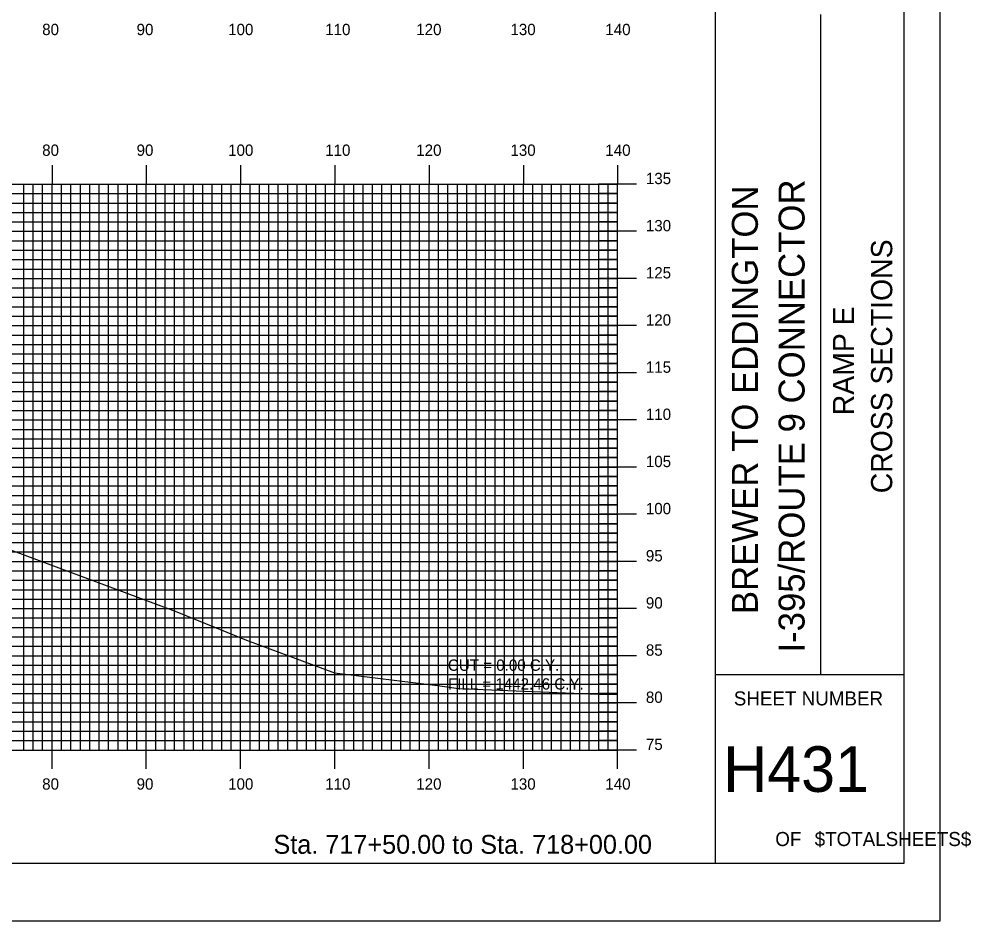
# Model space of a CAD drawing. Extents: x 857265 to 857608, y 364366 to 364586.
# Drawn here: x 857506.8 to 857607.8, y 364365.7 to 364461.3 of the extents above; entities that cross this region are included whole.
import ezdxf

# ---------------------------------------------------------------- set-up
doc = ezdxf.new("R2010")
doc.units = 0
for name, color, linetype in [('BORDER', 7, 'Continuous'), ('D_Text_Standard', 7, 'Continuous'), ('H_V ANNOTATION', 7, 'Continuous'), ('MAJOR', 7, 'Continuous'), ('MINOR', 7, 'Continuous'), ('PLOT BOUNDARY', 7, 'Continuous'), ('S_Roadway_Centerline', 7, 'Continuous')]:
    doc.layers.add(name, color=color, linetype=linetype)

msp = doc.modelspace()

# ---------------------------------------------------------------- linework, layer by layer
at = {"layer": 'BORDER'}
for p, q in [((857580.74, 364371.79), (857580.74, 364581.79)), ((857591.92, 364391.79), (857591.92, 364461.79)), ((857580.74, 364391.79), (857600.74, 364391.79))]:
    msp.add_line(p, q, dxfattribs=at)
msp.add_lwpolyline([(857280.74, 364371.79), (857600.74, 364371.79), (857600.74, 364581.79), (857280.74, 364581.79)], close=True, dxfattribs=at)
at = {"layer": 'MAJOR'}
for p, q in [((857510.34, 364445.79), (857510.34, 364443.79)), ((857520.34, 364445.79), (857520.34, 364443.79)), ((857530.34, 364445.79), (857530.34, 364443.79)), ((857540.34, 364445.79), (857540.34, 364443.79)), ((857550.34, 364445.79), (857550.34, 364443.79)), ((857560.34, 364445.79), (857560.34, 364443.79)), ((857570.34, 364445.79), (857570.34, 364443.79)), ((857290.34, 364443.79), (857570.34, 364443.79)), ((857290.34, 364443.79), (857570.34, 364443.79)), ((857510.34, 364383.79), (857510.34, 364443.79)), ((857520.34, 364383.79), (857520.34, 364443.79)), ((857530.34, 364383.79), (857530.34, 364443.79)), ((857540.34, 364383.79), (857540.34, 364443.79)), ((857550.34, 364383.79), (857550.34, 364443.79)), ((857560.34, 364383.79), (857560.34, 364443.79)), ((857572.34, 364443.79), (857568.33, 364443.79)), ((857570.34, 364383.79), (857570.34, 364443.79)), ((857570.34, 364383.79), (857570.34, 364443.79)), ((857290.34, 364438.79), (857570.34, 364438.79)), ((857572.34, 364438.79), (857568.33, 364438.79)), ((857290.34, 364433.79), (857570.34, 364433.79)), ((857572.34, 364433.79), (857568.33, 364433.79)), ((857290.34, 364428.79), (857570.34, 364428.79)), ((857572.34, 364428.79), (857568.33, 364428.79)), ((857290.34, 364423.79), (857570.34, 364423.79)), ((857572.34, 364423.79), (857568.33, 364423.79)), ((857290.34, 364418.79), (857570.34, 364418.79)), ((857572.34, 364418.79), (857568.33, 364418.79)), ((857290.34, 364413.79), (857570.34, 364413.79)), ((857572.34, 364413.79), (857568.33, 364413.79)), ((857290.34, 364408.79), (857570.34, 364408.79)), ((857572.34, 364408.79), (857568.33, 364408.79)), ((857290.34, 364403.79), (857570.34, 364403.79)), ((857572.34, 364403.79), (857568.33, 364403.79)), ((857290.34, 364398.79), (857570.34, 364398.79)), ((857572.34, 364398.79), (857568.33, 364398.79)), ((857290.34, 364393.79), (857570.34, 364393.79)), ((857572.34, 364393.79), (857568.33, 364393.79)), ((857290.34, 364388.79), (857570.34, 364388.79)), ((857572.34, 364388.79), (857568.33, 364388.79)), ((857290.34, 364383.79), (857570.34, 364383.79)), ((857290.34, 364383.79), (857570.34, 364383.79)), ((857510.34, 364381.78), (857510.34, 364383.79)), ((857520.34, 364381.78), (857520.34, 364383.79)), ((857530.34, 364381.78), (857530.34, 364383.79)), ((857540.34, 364381.78), (857540.34, 364383.79)), ((857550.34, 364381.78), (857550.34, 364383.79)), ((857560.34, 364381.78), (857560.34, 364383.79)), ((857572.34, 364383.79), (857568.33, 364383.79)), ((857570.34, 364381.78), (857570.34, 364383.79))]:
    msp.add_line(p, q, dxfattribs=at)
at = {"layer": 'MINOR'}
for p, q in [((857507.34, 364383.79), (857507.34, 364443.79)), ((857508.34, 364383.79), (857508.34, 364443.79)), ((857509.34, 364383.79), (857509.34, 364443.79)), ((857511.34, 364383.79), (857511.34, 364443.79)), ((857512.34, 364383.79), (857512.34, 364443.79)), ((857513.34, 364383.79), (857513.34, 364443.79)), ((857514.34, 364383.79), (857514.34, 364443.79)), ((857515.34, 364383.79), (857515.34, 364443.79)), ((857516.34, 364383.79), (857516.34, 364443.79)), ((857517.34, 364383.79), (857517.34, 364443.79)), ((857518.34, 364383.79), (857518.34, 364443.79)), ((857519.34, 364383.79), (857519.34, 364443.79)), ((857521.34, 364383.79), (857521.34, 364443.79)), ((857522.34, 364383.79), (857522.34, 364443.79)), ((857523.34, 364383.79), (857523.34, 364443.79)), ((857524.34, 364383.79), (857524.34, 364443.79)), ((857525.34, 364383.79), (857525.34, 364443.79)), ((857526.34, 364383.79), (857526.34, 364443.79)), ((857527.34, 364383.79), (857527.34, 364443.79)), ((857528.34, 364383.79), (857528.34, 364443.79)), ((857529.34, 364383.79), (857529.34, 364443.79)), ((857531.34, 364383.79), (857531.34, 364443.79)), ((857532.34, 364383.79), (857532.34, 364443.79)), ((857533.34, 364383.79), (857533.34, 364443.79)), ((857534.34, 364383.79), (857534.34, 364443.79)), ((857535.34, 364383.79), (857535.34, 364443.79)), ((857536.34, 364383.79), (857536.34, 364443.79)), ((857537.34, 364383.79), (857537.34, 364443.79)), ((857538.34, 364383.79), (857538.34, 364443.79)), ((857539.34, 364383.79), (857539.34, 364443.79)), ((857541.34, 364383.79), (857541.34, 364443.79)), ((857542.34, 364383.79), (857542.34, 364443.79)), ((857543.34, 364383.79), (857543.34, 364443.79)), ((857544.34, 364383.79), (857544.34, 364443.79)), ((857545.34, 364383.79), (857545.34, 364443.79)), ((857546.34, 364383.79), (857546.34, 364443.79)), ((857547.34, 364383.79), (857547.34, 364443.79)), ((857548.34, 364383.79), (857548.34, 364443.79)), ((857549.34, 364383.79), (857549.34, 364443.79)), ((857551.34, 364383.79), (857551.34, 364443.79)), ((857552.34, 364383.79), (857552.34, 364443.79)), ((857553.34, 364383.79), (857553.34, 364443.79)), ((857554.34, 364383.79), (857554.34, 364443.79)), ((857555.34, 364383.79), (857555.34, 364443.79)), ((857556.34, 364383.79), (857556.34, 364443.79)), ((857557.34, 364383.79), (857557.34, 364443.79)), ((857558.34, 364383.79), (857558.34, 364443.79)), ((857559.34, 364383.79), (857559.34, 364443.79)), ((857561.34, 364383.79), (857561.34, 364443.79)), ((857562.34, 364383.79), (857562.34, 364443.79)), ((857563.34, 364383.79), (857563.34, 364443.79)), ((857564.34, 364383.79), (857564.34, 364443.79)), ((857565.34, 364383.79), (857565.34, 364443.79)), ((857566.34, 364383.79), (857566.34, 364443.79)), ((857567.34, 364383.79), (857567.34, 364443.79)), ((857568.34, 364383.79), (857568.34, 364443.79)), ((857569.34, 364383.79), (857569.34, 364443.79)), ((857290.34, 364442.79), (857570.34, 364442.79)), ((857570.34, 364442.79), (857568.33, 364442.79)), ((857290.34, 364441.79), (857570.34, 364441.79)), ((857570.34, 364441.79), (857568.33, 364441.79)), ((857290.34, 364440.79), (857570.34, 364440.79)), ((857570.34, 364440.79), (857568.33, 364440.79)), ((857290.34, 364439.79), (857570.34, 364439.79)), ((857570.34, 364439.79), (857568.33, 364439.79)), ((857290.34, 364437.79), (857570.34, 364437.79)), ((857570.34, 364437.79), (857568.33, 364437.79)), ((857290.34, 364436.79), (857570.34, 364436.79)), ((857570.34, 364436.79), (857568.33, 364436.79)), ((857290.34, 364435.79), (857570.34, 364435.79)), ((857570.34, 364435.79), (857568.33, 364435.79)), ((857290.34, 364434.79), (857570.34, 364434.79)), ((857570.34, 364434.79), (857568.33, 364434.79)), ((857290.34, 364432.79), (857570.34, 364432.79)), ((857570.34, 364432.79), (857568.33, 364432.79)), ((857290.34, 364431.79), (857570.34, 364431.79)), ((857570.34, 364431.79), (857568.33, 364431.79)), ((857290.34, 364430.79), (857570.34, 364430.79)), ((857570.34, 364430.79), (857568.33, 364430.79)), ((857290.34, 364429.79), (857570.34, 364429.79)), ((857570.34, 364429.79), (857568.33, 364429.79)), ((857290.34, 364427.79), (857570.34, 364427.79)), ((857570.34, 364427.79), (857568.33, 364427.79)), ((857290.34, 364426.79), (857570.34, 364426.79)), ((857570.34, 364426.79), (857568.33, 364426.79)), ((857290.34, 364425.79), (857570.34, 364425.79)), ((857570.34, 364425.79), (857568.33, 364425.79)), ((857290.34, 364424.79), (857570.34, 364424.79)), ((857570.34, 364424.79), (857568.33, 364424.79)), ((857290.34, 364422.79), (857570.34, 364422.79)), ((857570.34, 364422.79), (857568.33, 364422.79)), ((857290.34, 364421.79), (857570.34, 364421.79)), ((857570.34, 364421.79), (857568.33, 364421.79)), ((857290.34, 364420.79), (857570.34, 364420.79)), ((857570.34, 364420.79), (857568.33, 364420.79)), ((857290.34, 364419.79), (857570.34, 364419.79)), ((857570.34, 364419.79), (857568.33, 364419.79)), ((857290.34, 364417.79), (857570.34, 364417.79)), ((857570.34, 364417.79), (857568.33, 364417.79)), ((857290.34, 364416.79), (857570.34, 364416.79)), ((857570.34, 364416.79), (857568.33, 364416.79)), ((857290.34, 364415.79), (857570.34, 364415.79)), ((857570.34, 364415.79), (857568.33, 364415.79)), ((857290.34, 364414.79), (857570.34, 364414.79)), ((857570.34, 364414.79), (857568.33, 364414.79)), ((857290.34, 364412.79), (857570.34, 364412.79)), ((857570.34, 364412.79), (857568.33, 364412.79)), ((857290.34, 364411.79), (857570.34, 364411.79)), ((857570.34, 364411.79), (857568.33, 364411.79)), ((857290.34, 364410.79), (857570.34, 364410.79)), ((857570.34, 364410.79), (857568.33, 364410.79)), ((857290.34, 364409.79), (857570.34, 364409.79)), ((857570.34, 364409.79), (857568.33, 364409.79)), ((857290.34, 364407.79), (857570.34, 364407.79)), ((857570.34, 364407.79), (857568.33, 364407.79)), ((857290.34, 364406.79), (857570.34, 364406.79)), ((857570.34, 364406.79), (857568.33, 364406.79)), ((857290.34, 364405.79), (857570.34, 364405.79)), ((857570.34, 364405.79), (857568.33, 364405.79)), ((857290.34, 364404.79), (857570.34, 364404.79)), ((857570.34, 364404.79), (857568.33, 364404.79)), ((857290.34, 364402.79), (857570.34, 364402.79)), ((857570.34, 364402.79), (857568.33, 364402.79)), ((857290.34, 364401.79), (857570.34, 364401.79)), ((857570.34, 364401.79), (857568.33, 364401.79)), ((857290.34, 364400.79), (857570.34, 364400.79)), ((857570.34, 364400.79), (857568.33, 364400.79)), ((857290.34, 364399.79), (857570.34, 364399.79)), ((857570.34, 364399.79), (857568.33, 364399.79)), ((857290.34, 364397.79), (857570.34, 364397.79)), ((857570.34, 364397.79), (857568.33, 364397.79)), ((857290.34, 364396.79), (857570.34, 364396.79)), ((857570.34, 364396.79), (857568.33, 364396.79)), ((857290.34, 364395.79), (857570.34, 364395.79)), ((857570.34, 364395.79), (857568.33, 364395.79)), ((857290.34, 364394.79), (857570.34, 364394.79)), ((857570.34, 364394.79), (857568.33, 364394.79)), ((857290.34, 364392.79), (857570.34, 364392.79)), ((857570.34, 364392.79), (857568.33, 364392.79)), ((857290.34, 364391.79), (857570.34, 364391.79)), ((857570.34, 364391.79), (857568.33, 364391.79)), ((857290.34, 364390.79), (857570.34, 364390.79)), ((857570.34, 364390.79), (857568.33, 364390.79)), ((857290.34, 364389.79), (857570.34, 364389.79)), ((857570.34, 364389.79), (857568.33, 364389.79)), ((857290.34, 364387.79), (857570.34, 364387.79)), ((857290.34, 364386.79), (857570.34, 364386.79)), ((857570.34, 364387.79), (857568.33, 364387.79)), ((857570.34, 364386.79), (857568.33, 364386.79)), ((857290.34, 364385.79), (857570.34, 364385.79)), ((857570.34, 364385.79), (857568.33, 364385.79)), ((857290.34, 364384.79), (857570.34, 364384.79)), ((857570.34, 364384.79), (857568.33, 364384.79))]:
    msp.add_line(p, q, dxfattribs=at)
at = {"layer": 'PLOT BOUNDARY'}
msp.add_lwpolyline([(857264.55, 364365.67), (857604.55, 364365.67), (857604.55, 364585.67), (857264.55, 364585.67)], close=True, dxfattribs=at)
at = {"layer": 'S_Roadway_Centerline'}
msp.add_lwpolyline([(857404.88, 364432.81), (857411.36, 364431.08), (857411.78, 364430.91), (857413.4, 364430.11), (857428.18, 364423.21), (857439.25, 364418.03), (857445.73, 364414.89), (857448.9, 364413.49), (857460.95, 364409.69), (857461.3, 364409.58), (857461.44, 364409.57), (857478.38, 364408.37), (857486.77, 364407.96), (857495.98, 364407.19), (857502.27, 364406.36), (857523.41, 364398.52), (857530.98, 364395.44), (857540.32, 364391.98), (857551.23, 364390.63), (857553.46, 364390.3), (857568.3, 364389.73), (857569.71, 364389.72), (857570.34, 364389.72)], dxfattribs=at)

# ---------------------------------------------------------------- texts
at = {"layer": 'BORDER'}
for s, height, p in [('BREWER TO EDDINGTON', 2.7557, (857585.22, 364398.2)), ('I-395/ROUTE 9 CONNECTOR', 2.7557, (857590.18, 364394.12)), ('CROSS SECTIONS', 2.25, (857599.48, 364411.01)), ('RAMP E', 2.25, (857595.43, 364419.29))]:
    msp.add_text(s, height=height, rotation=90, dxfattribs=at).set_placement(p)
for s, height, p in [('SHEET NUMBER', 1.4905, (857582.67, 364388.52)), ('H431', 4.839, (857581.54, 364379.35)), ('OF', 1.491, (857587.07, 364373.61)), ('$TOTALSHEETS$', 1.4905, (857591.25, 364373.61))]:
    msp.add_text(s, height=height, dxfattribs=at).set_placement(p)
at = {"layer": 'D_Text_Standard'}
for s, p in [('CUT = 0.00 C.Y.', (857552.34, 364392.19)), ('FILL = 1442.46 C.Y.', (857552.34, 364390.2))]:
    msp.add_text(s, height=1.2, dxfattribs=at).set_placement(p)
at = {"layer": 'H_V ANNOTATION'}
for s, height, p in [('80', 1.2, (857509.29, 364459.59)), ('90', 1.2, (857519.31, 364459.59)), ('100', 1.2, (857529.02, 364459.59)), ('110', 1.2, (857539.32, 364459.59)), ('120', 1.2, (857548.98, 364459.59)), ('130', 1.2, (857558.97, 364459.59)), ('140', 1.2, (857569.04, 364459.59)), ('80', 1.2, (857509.29, 364446.79)), ('90', 1.2, (857519.31, 364446.79)), ('100', 1.2, (857529.02, 364446.79)), ('110', 1.2, (857539.32, 364446.79)), ('120', 1.2, (857548.98, 364446.79)), ('130', 1.2, (857558.97, 364446.79)), ('140', 1.2, (857569.04, 364446.79)), ('135', 1.2, (857573.34, 364443.79)), ('130', 1.2, (857573.34, 364438.79)), ('125', 1.2, (857573.34, 364433.79)), ('120', 1.2, (857573.34, 364428.79)), ('115', 1.2, (857573.34, 364423.79)), ('110', 1.2, (857573.34, 364418.79)), ('105', 1.2, (857573.34, 364413.79)), ('100', 1.2, (857573.34, 364408.79)), ('95', 1.2, (857573.34, 364403.79)), ('90', 1.2, (857573.34, 364398.79)), ('85', 1.2, (857573.34, 364393.79)), ('80', 1.2, (857573.34, 364388.79)), ('75', 1.2, (857573.34, 364383.79)), ('80', 1.2, (857509.29, 364379.59)), ('90', 1.2, (857519.31, 364379.59)), ('100', 1.2, (857529.02, 364379.59)), ('110', 1.2, (857539.32, 364379.59)), ('120', 1.2, (857548.98, 364379.59)), ('130', 1.2, (857558.97, 364379.59)), ('140', 1.2, (857569.04, 364379.59)), ('Sta. 717+50.00 to Sta. 718+00.00', 2.0004, (857533.83, 364372.79))]:
    msp.add_text(s, height=height, dxfattribs=at).set_placement(p)

doc.saveas('drawing.dxf')
